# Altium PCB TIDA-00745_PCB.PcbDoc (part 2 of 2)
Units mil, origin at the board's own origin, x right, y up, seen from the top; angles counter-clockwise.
Board outline 7745 x 3490 mil, 4 copper layers (Top Layer, Signal Layer 1, Signal Layer 2, Bottom Layer), stack 61.2 mil thick; 181 components, 60 nets, 404 pads, 89 vias.
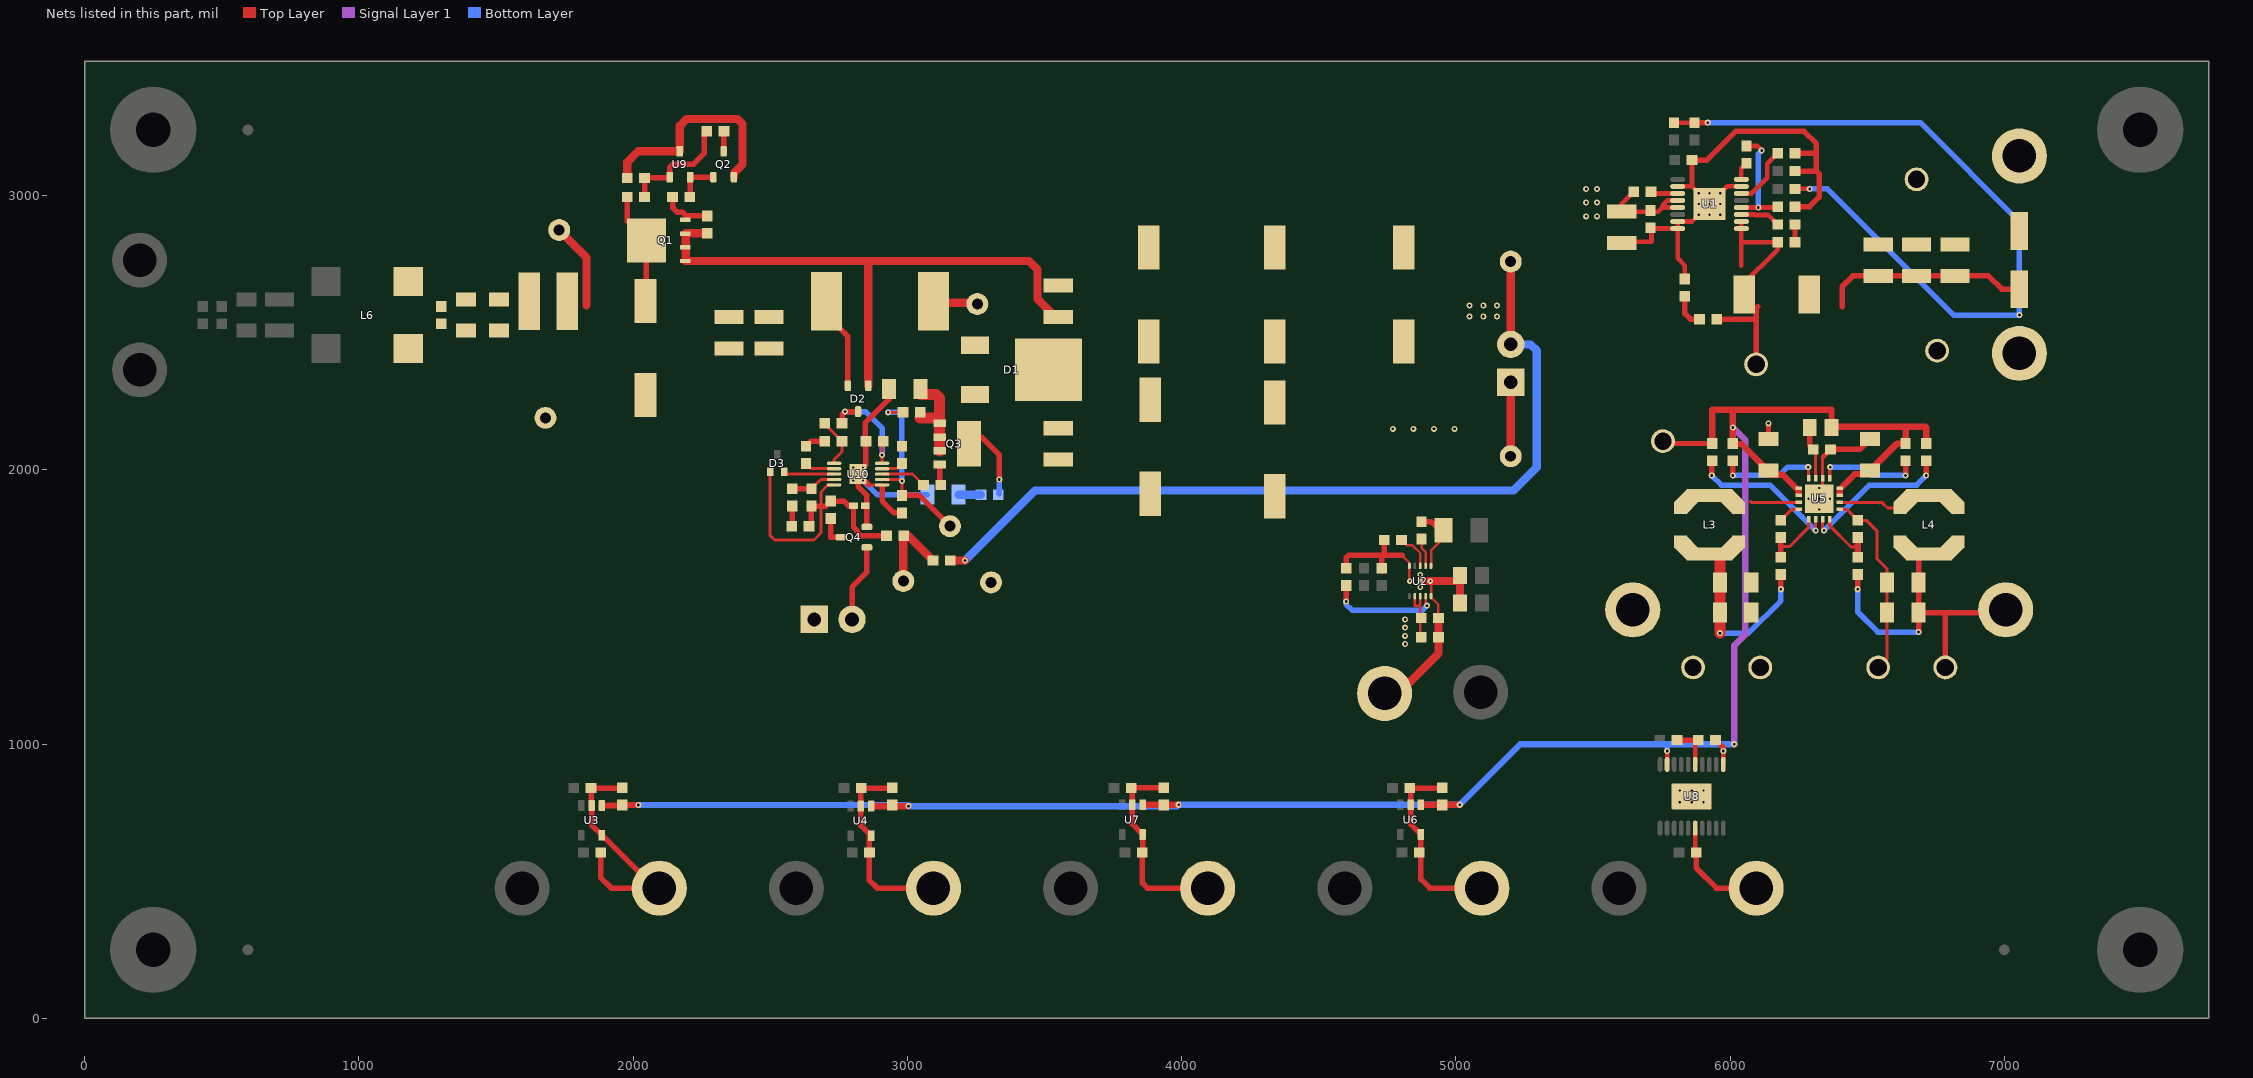
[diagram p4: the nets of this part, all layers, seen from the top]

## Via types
v1: diameter 22, hole 10, Top Layer to Bottom Layer, 60 vias
v2: diameter 20, hole 8, Top Layer to Bottom Layer, 29 vias

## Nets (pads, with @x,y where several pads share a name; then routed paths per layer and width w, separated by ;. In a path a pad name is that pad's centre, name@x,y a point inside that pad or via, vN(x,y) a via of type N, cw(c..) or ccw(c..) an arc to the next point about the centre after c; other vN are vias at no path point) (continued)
GND: C1.2 C2.2 C3.2 C5.2 C6.2 C7.2 C8.2 C9.2 C10.2 C12.2 C13.2 C14.1 C15.1 C16.2 C17.2 C18.2 C19.2 C20.2 C21.2 C22.2 C23.2 C24.2 C25.2 C26.2 C27.2 C28.2 C29.2 C30.2 C31.2 C32.2 C33.2 C34.2 C35.2 C36.2 C37.2 C41.2 C43.2 C44.2 C45.2 C46.2 C47.2 C48.2 C49.2 C50.2 C51.2 C52.2 C53.2 C54.2 C55.1 C56.2 C57.2 C58.2 C61.2 CVCC1.1 D4.2 J1.1 J2.1 L6.3 Q2.2 Q4.2 R6.1 R8.1 R10.1 R11.1 R19.1 R20.1 R25.1 R29.1 R30.1 TP4.1 TP5.1 TP7.1 TP10.1 TP11.1 TP17.1 TP18.1 TP20.1 TP21.1 TP22.1 TP26.1 TP28.1 TP32.1 U1.7 U1.10 U1.15 U1.16 U1.17 U2.5 U2.10 U2.11 U3.2 U3.5 U4.2 U4.5 U5.4 U5.9 U5.14 U5.17 U6.2 U6.5 U7.2 U7.5 U8.6 U8.15 U8.21 U9.3 U10.6 U10.11 | length 10121.7
  Top Layer w9: 4803.66,1688.5 4830.63,1661.53 U2.5@4830.63,1650.12 4830.63,1605.63 ; 4909.37,1584.37 U2.10@4909.37,1539.88 4910,1539.25 4910,1535 4936.5,1508.5 C14.1@4936.5,1460
  Top Layer w11: 2859.37,1945.63 U10.6@2907.6,1945.63 ; R19.1@6185,1816.5 6225.12,1856.61 U5.4@6250.2,1856.61 ; U5.17@6337.8,1907.8 U5.14@6337.8,1969.8 6337.8,2046.3 ; U5.9@6399.8,1856.61 6424.88,1856.61 R20.1@6465,1816.5 6496.5,1816.5 6536.3,1776.7 6536.3,1675.28 6572.91,1638.66 C33.2@6572.91,1590 C34.2@6572.91,1480 6572.91,1312.91 TP21.1@6540,1280
  Top Layer w15: 6337.8,2046.3 C24.2@6366.5,2075
  Top Layer w17: C1.2@5605,2827.91 5609.02,2831.93 5713.07,2831.93 5713.07,2880.43 U1.16@5808.86,2880.43 ; U1.10@5808.86,3033.98 5861.02,3033.98 v2(5925,2970) ; C9.2@5835,2696.5 5835,2745.5 5808.86,2771.64 U1.16@5808.86,2880.43 ; R8.1@5861.02,3129.53 R8.1@5861.5,3130 ; U8.6@5872.8,693.86 5872.8,608.7 C36.2@5876.5,605 ; U8.15@5872.8,926.14 C37.2@5872.8,1015 ; U1.7@6041.14,3033.98 5988.98,3033.98 v2(5925,2970) ; U1.16@5808.86,2880.43 U1.15@5808.86,2906.02 5861.02,2906.02 v2(5885.63,2930.63) v2(5925,2970)
  Top Layer w20: C17.2@1881.5,605 1881.5,513.5 1920,475 TP10.1@2078.86,475 ; C20.2@1960,841.5 1958.5,840 C16.2@1846.5,840 1846.5,778.23 U3.2@1848.45,776.28 1849.53,775.2 1849.53,704.33 U3.5@1885.85,668.01 TP10.1@2078.86,475 ; TP10.1@2095,475 TP10.1@2078.86,475 ; C58.2@2630,2086.5 2648.5,2105 C55.1@2698.5,2105 ; v2(2837.72,2008.62) 2848.5,2019.41 C56.2@2848.5,2105 2846,2107.5 2846,2171 2932.91,2257.91 R29.1@2932.91,2275 ; Q4.2@2852.24,1792.4 2852.24,1907.65 2820,1939.9 v2(2820,1985) 2859.37,1945.63 ; U10.6@2907.6,1941.54 2907.6,1887.4 2951.5,1843.5 C61.2@2980,1843.5 ; C21.2@2943.5,840 C18.2@2831.5,840 2830,838.5 U4.2@2830,774.13 2830,703.27 2861.5,671.77 C19.2@2861.5,605 2861.5,503.5 2890,475 TP11.1@3095,475 ; C27.2@3816.5,840 3820,836.5 U7.2@3820,779.13 3820,708.27 U7.5@3857.4,670.87 3857.4,605.91 C28.2@3856.5,605 3856.5,493.5 3875,475 TP18.1@4095,475 ; C27.2@3817.99,841.5 C30.2@3935,841.5 ; R10.1@4600,1641.5 4600,1680 4608.5,1688.5 4740,1688.5 ; R11.1@4730,1631.5 R11.1@4730,1641.5 4730,1683.5 ; CVCC1.1@4738.5,1745 4738.5,1690 4740,1688.5 ; 4803.66,1688.5 4740,1688.5 ; C25.2@4831.5,840 C29.2@4948.5,840 ; C25.2@4835,836.5 U6.2@4835,779.13 4835,708.27 U6.5@4872.4,670.87 4872.4,507.6 4905,475 TP17.1@5095,475 ; C35.2@5806.5,1015 C37.2@5883.5,1015 ; 5861.02,3033.98 R8.1@5861.02,3129.53 ; R8.1@5861.5,3130 5915,3130 6020,3235 6270,3235 6315,3190 6315,3090 ; C36.2@5876.5,605 5876.5,548.5 5950,475 TP22.1@6095,475 ; C22.2@6140,2112.09 v1(6140,2170) ; C10.2@6236.5,2960 6290,2960 6325,2995 6325,3080 6315,3090 ; C3.2@6236.5,3090 6315,3090 ; R6.1@6236.5,3155 6315,3155 ; v2(6325,1895) U5.17@6337.8,1907.8 ; C24.2@6366.5,2075 6472.91,2075 C23.2@6510,2112.09
  Top Layer w30: R25.1@1978.5,3065 1978.5,3123.5 2017.24,3162.24 U9.3@2170,3162.24 2170,3255 2195,3280 2380,3280 2398.9,3261.1 2398.9,3114.03 2367.4,3082.54 Q2.2@2367.4,3067.76 ; TP7.1@4740,1185 4790,1185 4936.5,1331.5 C15.1@4936.5,1390 C14.1@4936.5,1460 ; 4890,1595 v2(4907.4,1595) C13.2@5010,1595 ; C12.2@5015,1515 C13.2@5015,1615 ; TP28.1@5200,2050 J1.1@5200,2320
  Bottom Layer w20: v2(2837.72,1961.38) 2889.09,1910 R30.1@3072.91,1910
  other v2: 5816.69,788.35 5860,788.35 5903.31,788.35 5816.69,831.65 5860,831.65 5903.31,831.65 4870,1572.36 4832.6,1595 4870,1617.64 6325,1855.63 6285.63,1895 6364.37,1895 6325,1934.37 2802.28,1961.38 2802.28,2008.62 5925,2930.63 5964.37,2930.63 5885.63,2970 5964.37,2970 5885.63,3009.37 5925,3009.37 5964.37,3009.37
Net1_1: 1.1 C31.1 C32.1 L3.1 R16.2 TP12.1 | length 662.4
  Top Layer w20: v1(6185,1565) R16.2@6185,1618.5
  Top Layer w40: v1(5962.91,1405) C31.1@5962.91,1590 5962.91,1679.61 L3.1@5978,1694.7
  Bottom Layer w20: v1(5962.91,1405) 6067,1405 6185,1523 v1(6185,1565)
Net2_1: 2.1 C33.1 C34.1 L4.2 R18.2 TP15.1 | length 1183.8
  Top Layer w20: v1(6465,1565) R18.2@6465,1618.5 ; L4.2@6680,1693.7 6687.09,1686.61 C34.1@6687.09,1480 ; v1(6687.09,1409) C34.1@6687.09,1480 ; 2.1@6785,1280 6785,1480 ; TP15.1@6995,1480 6785,1480 ; C34.1@6687.09,1480 6785,1480
  Bottom Layer w20: v1(6465,1565) 6465,1483 6539,1409 v1(6687.09,1409)
NetC4_1: C4.1 R4.1 | length 65
  Top Layer w17: R4.1@6236.5,2830 C4.1@6236.5,2895
NetC4_2: C4.2 U1.3 | length 159.4
  Top Layer w17: U1.3@6041.14,2931.61 6089.67,2931.61 6091.46,2929.83 6138.67,2929.83 C4.2@6173.5,2895 C4.2@6165.12,2886.61
NetC9_1: C9.1 R5.1 | length 125.3
  Top Layer w20: C9.1@5835,2633.5 5835,2570 5855,2550 R5.1@5888.5,2550
NetC24_1: C24.1 R13.1 U5.15 | length 194.4
  Top Layer w11: C24.1@6303.5,2075 6312.2,2066.3 U5.15@6312.2,1969.8
  Top Layer w20: R13.1@6290,2155 6290,2088.5 C24.1@6303.5,2075
NetC43_1: C43.1 C44.1 C45.1 L6.4 LF1.1
NetC55_2: C55.2 R26.1 U10.1 | length 183.8
  Top Layer w11: R26.1@2698.5,2170 2698.5,2167.99 C55.2@2761.5,2105 2761.5,2066.5 2732.4,2037.4 U10.1@2732.4,2024.37
NetC56_1: C56.1 D2.3 R26.2 U10.10 | length 435
  Top Layer w11: U10.10@2907.6,2024.37 v1(2907.6,2055) 2907.6,2101.1 C56.1@2911.5,2105
  Top Layer w20: R26.2@2761.5,2170 2761.5,2202.01 v1(2772.24,2212.76) D2.3@2820,2212.76
  Bottom Layer w20: v1(2772.24,2212.76) 2847.24,2212.76 2907.6,2152.4 v1(2907.6,2055)
NetC57_1: C57.1 U10.9 | length 80.2
  Top Layer w11: U10.9@2907.6,2004.69 2961.18,2004.69 C57.1@2980,2023.5
NetC58_1: C58.1 U10.2 | length 110.2
  Top Layer w11: C58.1@2630,2023.5 2648.82,2004.69 U10.2@2732.4,2004.69
NetC59_1: C59.1 D1.1 D1.3 L5.2 Q3.5 TP29.1 | length 395.6
  Top Layer w20: 3269.98,2119.99 3335,2054.97 v1(3335,1965)
  Top Layer w30: L5.2@3094.88,2615 3099.88,2610 TP29.1@3255,2610
  Bottom Layer w20: C59.1@3335,1913.5 v1(3335,1965)
NetC59_2: C59.2 R30.2 | length 81.4
  Bottom Layer w30: R30.2@3187.09,1910 C59.2@3268.5,1910
NetC60_1: C60.1 C62.2 U10.4 | length 166.4
  Top Layer w11: C62.2@2650,1931.5 2683.82,1965.31 U10.4@2732.4,1965.31
  Top Layer w20: C60.1@2580,1931.5 C62.2@2650,1931.5
NetC60_2: C60.2 R31.2 | length 74.1
  Top Layer w20: R31.2@2578.5,1795 2580,1796.5 C60.2@2580,1868.5
NetC61_1: C61.1 R28.1 TP30.1 U10.7 | length 699.7
  Top Layer w11: U10.7@2907.6,1965.31 2974.68,1965.31 v1(2980,1960) C61.1@2980,1906.5 ; v1@2935,2210 R28.1@2983.5,2210 R28.1@2988.5,2210
  Top Layer w20: C61.1@2980,1906.5 2980,1908.43 3041.57,1908.43 TP30.1@3155,1795
  Bottom Layer w20: v1(2930,2210) 2970,2210 2980,2200 v1(2980,1960)
NetC62_1: C62.1 D3.1 D4.1 R31.1 R32.1 R34.2 U10.5 | length 1089.4
  Top Layer w11: D3.1@2499.41,1993.5 2499.41,1760.59 2515,1745 2659.38,1745 2685,1770.62 2685,1868.5 2685,1920 2710.63,1945.63 U10.5@2732.4,1945.63
  Top Layer w20: R31.1@2650,1803.5 C62.1@2650,1868.5 2685,1868.5 2702.01,1868.5 R34.2@2720,1886.5 2768.5,1886.5 2785,1870 D4.1@2803.35,1870 2803.35,1791.65 2814.68,1780.31 2814.68,1776.65 2831.33,1760 R32.1@2923.5,1760
NetCBOOT1_1: CBOOT1.1 U2.2 | length 105.3
  Top Layer w9: CBOOT1.1@4875,1748.5 4875,1715.36 4889.69,1700.67 U2.2@4889.69,1650.12 U2.2@4890.56,1650.12
NetCBOOT1_2: CBOOT1.2 L2.1 U2.1 | length 233.1
  Top Layer w9: U2.1@4909.37,1650.12 4909.37,1706.26 4955.04,1751.93 L2.1@4955.04,1765
  Top Layer w20: CBOOT1.2@4875,1811.5 4908.54,1811.5 L2.1@4955.04,1765
NetCVCC1_2: CVCC1.2 U2.3 | length 135
  Top Layer w9: CVCC1.2@4801.5,1745 4821.29,1725.2 4841.29,1725.2 4870,1696.5 U2.3@4870,1650.12
NetD3_2: D3.2 U10.3 | length 185.3
  Top Layer w11: D3.2@2550.59,1993.5 2559.09,1985 U10.3@2732.4,1985
NetJ2_2: J2.2 Q4.1 | length 285.1
  Top Layer w20: J2.2@2798,1455 2798,1573 2852.24,1627.24 Q4.1@2852.24,1717.6
NetL3_2: L3.2 U5.3 | length 178
  Top Layer w11: 6073.67,1885.68 6077.15,1882.2 U5.3@6250.2,1882.2
NetL4_1: L4.1 U5.10 | length 227.5
  Top Layer w11: U5.10@6399.8,1882.2 6553.01,1882.2 6573.7,1861.52 L4.1@6618.7,1861.52
NetQ1_4: Q1.4 R21.1 R24.2 | length 177.4
  Top Layer w20: R24.2@2143.5,2995 2143.5,2956.5 2160,2940 2180,2940 2193.5,2926.5 R21.1@2270,2926.5
NetQ2_1: Q2.1 R24.1 U9.2 | length 157
  Top Layer w20: R24.1@2207.4,2995.91 U9.2@2207.4,3067.76 Q2.1@2292.6,3067.76
NetQ2_3: Q2.3 R22.1 | length 73.4
  Top Layer w20: Q2.3@2330,3162.24 2330,3233.5 R22.1@2331.5,3235
NetQ3_1: Q3.1 Q3.2 Q3.3 R28.2 R29.2 | length 319.4
  Top Layer w40: 3046.5,2190 3097.72,2190 ; R29.2@3047.09,2275 3105,2275 3117.72,2262.28 Q3.1@3117.72,2170 Q3.2@3117.72,2120 Q3.3@3117.72,2070
NetQ3_4: Q3.4 R27.2 | length 76.6
  Top Layer w20: Q3.4@3117.72,2020 3117.72,1948.78 R27.2@3121.5,1945
NetQ4_3: Q4.3 R34.1 | length 106.3
  Top Layer w20: R34.1@2720,1823.5 2720,1755 Q4.3@2757.76,1755
NetR2_1: R2.1 U1.11 | length 98.8
  Top Layer w17: R2.1@5711.5,3005 5714.88,3008.39 U1.11@5808.86,3008.39
NetR3_1: R3.1 U1.8 | length 66.7
  Top Layer w17: U1.8@6041.14,3059.57 6041.14,3099.65 R3.1@6060,3118.5
NetR10_2: R10.2 U2.9 | length 416.3
  Top Layer w9: U2.9@4889.69,1539.88 4889.69,1510.31 v1(4895,1505)
  Top Layer w20: v1(4600,1520) R10.2@4600,1578.5
  Bottom Layer w20: v1(4600,1520) 4600,1510 4621.46,1488.54 4878.54,1488.54 v1(4895,1505)
NetR12_1: R12.1 U5.16 | length 378.5
  Top Layer w11: U5.16@6286.61,1969.8 v1@6286.61,2008.39
  Top Layer w20: v1(6010,1980) R12.1@6010,2033.5
  Bottom Layer w20: v1@6011,1980 6180,1980 6210,2010 v1(6285,2010)
NetR14_1: R14.1 U5.13 | length 378.9
  Top Layer w11: U5.13@6363.39,1969.8 6363.39,2008.39 v1(6365,2010)
  Top Layer w20: v1(6640,1980) R14.1@6640,2030.57
  Bottom Layer w20: v1(6365,2010) 6488.01,2010 6518.01,1980 v1(6640,1980)
NetR15_2: R15.2 U5.6 | length 554.1
  Top Layer w11: v1(6312,1779) 6312,1819.99 U5.6@6312.2,1820.2
  Top Layer w20: v1(5933,1980) R15.2@5933,2030.57
  Bottom Layer w20: v1(5933,1980) 5968,1945 6146,1945 v1(6312,1779)
NetR16_1: R16.1 R19.2 U5.5 | length 231
  Top Layer w11: 6186,1721 6217,1721 6286.61,1790.61 U5.5@6286.61,1820.2
  Top Layer w20: R16.1@6185,1681.5 R19.2@6185,1753.5
NetR17_2: R17.2 U5.7 | length 552.7
  Top Layer w11: U5.7@6337.8,1820.2 6337.8,1783.2 v1(6342,1779)
  Top Layer w20: v1(6715,1980) R17.2@6715,2033.5
  Bottom Layer w20: v1(6342,1779) 6508,1945 6680,1945 v1(6715,1980)
NetR18_1: R18.1 R20.2 U5.8 | length 229.7
  Top Layer w11: U5.8@6363.39,1820.2 6363.39,1797.39 6363,1797 6441,1719 6465,1719
  Top Layer w23: R18.1@6465,1681.5 6465,1719 R20.2@6465,1753.5
NetR22_2: R22.2 R23.1 R25.2 U9.1 | length 429.7
  Top Layer w20: R23.1@2041.5,2995 R25.2@2041.5,3065 2129.84,3065 U9.1@2132.6,3067.76 2132.6,3102.6 2145,3115 2220,3115 2260,3155 2260,3226.5 R22.2@2268.5,3235
NetR27_1: R27.1 U10.8 | length 167.5
  Top Layer w11: U10.8@2907.6,1985 3018.5,1985 R27.1@3058.5,1945
NetR32_2: R32.2 R33.1 TP31.1 | length 309.9
  Top Layer w30: TP31.1@2985,1595 2985,1758.5 R32.2@2986.5,1760 3003.5,1760 R33.1@3093.5,1670
SW: L1.1 R4.2 R5.2 TP2.1 U1.1 U1.2 | length 852.5
  Top Layer w17: 6041.14,2744.64 U1.1@6041.14,2880.43 U1.2@6041.14,2906.02 ; L1.1@6045,2675 6173.5,2803.5 R4.2@6173.5,2830 6046.14,2830
  Top Layer w20: R5.2@5951.5,2550 6095,2550 ; TP2.1@6095,2385 6095,2550 ; 6100,2595 6095,2590 6095,2550
SYNC: R6.2 U1.6 | length 223.2
  Top Layer w17: U1.6@6041.14,3008.39 6078.21,3008.39 6135,3065.18 6135,3116.5 R6.2@6173.5,3155
VCC: C10.1 R3.2 U1.4 | length 407
  Top Layer w17: U1.4@6041.14,2957.2 v1(6102.8,2957.2) C10.1@6173.5,2957.2 ; R3.2@6060,3181.5 6098.5,3181.5 v1(6115,3165)
  Bottom Layer w20: v1(6102.8,2957.2) 6102.8,3152.8 v1(6115,3165)
VIN+: C41.1 C46.1 C47.1 D2.2 L5.1 LF1.2 Q1.5 R23.2 TP23.1 | length 1065
  Top Layer w20: R23.2@1978.5,2995 1978.5,2906.5 Q1.5@2047.99,2837 2047.99,2619.25 C41.1@2045,2616.26 ; L5.1@2705.12,2615 2705.12,2564.88 2782.6,2487.4 D2.2@2782.6,2307.24
  Top Layer w30: TP23.1@1730,2875 1830,2775 1830,2600
VOUT: C5.1 C6.1 C7.1 C8.1 C11.1 C20.1 C21.1 C22.1 C23.1 C29.1 C30.1 C37.1 L1.2 R1.2 R7.2 R12.2 R13.2 R14.2 R15.1 R17.1 TP1.1 TP3.1 TP16.1 U3.1 U4.1 U5.1 U5.2 U5.11 U5.12 U6.1 U7.1 U8.11 U8.19 | length 11584.7
  Top Layer w17: U8.19@5770.43,926.14 v1(5770.43,975) ; R7.2@5795,3266.5 C11.1@5870,3266.5 ; U8.11@5975.16,926.14 v1@5975.16,975 ; R1.2@6236.5,3025 v1(6290,3025)
  Top Layer w20: TP16.1@5755,2105 5763.5,2096.5 R15.1@5935,2096.5 ; C11.1@5870,3266.5 v1(5918.5,3266.5) ; C37.1@5946.5,1015 5975.08,986.42 v1(5975.08,975) ; 6408.11,2595 6408.11,2668.11 6447.91,2707.91 C6.1@6540,2707.91 C7.1@6680,2707.91 C8.1@6820,2707.91 6942.09,2707.91 6990.81,2659.19 C5.1@7054.51,2659.19
  Top Layer w23: U3.1@1885.85,776.28 C20.1@1957.78,776.28 ; C20.1@1960,778.5 v1(2018.5,778.5) ; U4.1@2867.4,774.13 v1(3004.13,774.13) ; U7.1@3857.4,779.13 v1(3989.13,779.13) ; U6.1@4872.4,779.13 v1(5014.13,779.13) ; R15.1@5935,2096.5 5935,2220 6010,2220 ; R12.2@6010,2091.5 R12.2@6010,2095 ; C22.1@6140,1982.91 6192.09,1982.91 6250.2,1924.8 6250.2,1915 ; C22.1@6140,1997.91 6137.09,1997.91 6040,2095 R12.2@6010,2095 ; 6399.8,1916 6399.8,1929.8 6455,1985 6497.09,1985 C23.1@6510,1997.91 6608.58,2096.5 R14.2@6640,2096.5 ; R14.2@6636.42,2087.91 6636.42,2099.45 6640,2103.03 6640,2157.05 ; R17.1@6715,2096.5 6715,2155 6712.95,2157.05 6640,2157.05 ; R12.2@6010,2095 R12.2@6010,2096.5 v1(6010,2155) 6010,2220 ; 6010,2220 6370,2220 R13.2@6370,2155 6372.05,2157.05 6640,2157.05
  Signal Layer 1 w23: v1(6010,2155) 6055,2110 6055,1400 6015,1360 v1(6015,1000)
  Bottom Layer w20: v1(5770.43,975) 5770.43,999.41 ; v1(5918.5,3266.5) 6693.5,3266.5 7055,2905 v1(7055,2565) 6815,2565 6355,3025 v1(6290,3025) ; v1(5975.08,975) 5975.08,999.41
  Bottom Layer w23: v1(2018.5,778.5) 2999.76,778.5 v1(3004.13,774.13) 3984.13,774.13 v1(3989.13,779.13) v1(5014.13,779.13) 5235,1000 v1(6015,1000)
VS: C1.1 C2.1 C14.2 C15.2 C48.1 C49.1 C50.1 C51.1 C52.1 C53.1 C54.1 D1.4 D2.1 J1.2 Q1.1 Q1.2 Q1.3 R2.2 R21.2 R33.2 TP24.1 U1.12 U1.13 U2.7 U2.8 | length 5830.4
  Top Layer w9: U2.7@4850.31,1539.88 4850.31,1505.31 4850.63,1505 4870,1505 ; U2.8@4870,1539.88 4870,1505 ; C15.2@4873.5,1390 4870,1393.5 4870,1505
  Top Layer w17: R2.2@5648.5,3015 5605,2971.5 C1.1@5605,2942.09 5737.09,2942.09 5757.44,2962.44 ; U1.13@5808.86,2957.2 5762.68,2957.2 5754.94,2964.94 5772.8,2982.8 U1.12@5808.86,2982.8
  Top Layer w30: R21.2@2270,2863.5 2191.62,2863.5 2191.62,2763.5 Q1.1@2190.12,2762 2855,2762 ; D2.1@2857.4,2307.24 2857.4,2759.6 2855,2762 ; R33.2@3156.5,1670 v1(3210,1670) ; C52.1@3550,2557.91 3539.69,2557.91 3473.98,2623.62 3473.98,2731.02 3443,2762 2855,2762 ; J1.2@5200,2458 TP24.1@5200,2760
  Bottom Layer w30: v1(3210,1670) 3465,1925 5210,1925 5295,2010 5295,2435 5272,2458 J1.2@5200,2458
  other v1: 4815,1365 4815,1395 4815,1425 4815,1455 4770,2150 4845,2150 4920,2150 4995,2150 5050,2560 5100,2560 5150,2560 5050,2600 5100,2600 5150,2600 5475,2925 5515,2925 5475,2975 5515,2975 5475,3025 5515,3025
pads on no net: D3.3 FID1.1 FID2.1 FID3.1 FID4.1 FID5.1 FID6.1 H1.1 H2.1 H3.1 H4.1 LBL1.0 U1.14 U2.6 U8.2 U8.3 U8.4 U8.5 U8.7 U8.8 U8.9 U8.12 U8.13 U8.14 U8.16 U8.17 U8.18

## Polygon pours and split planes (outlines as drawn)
VS on Top Layer "Top Layer-VS" (solid, remove dead copper, pour order 28): 4875,1600 4875,1538.54 4900,1538.54 4900,1405 4895,1400 4790,1400 4790,1540 4790,1555 4805,1555 4850,1555 4848.17,1557.46 4848.17,1605 4875,1605
GND on Top Layer "Top Layer-GND" (solid, remove dead copper, pour order 38): 6390,1860 6550,1860 6575,1835 6610,1800 6610,1650 6610,1215 6615,1210 6610,1215 6500,1215 6500,1778.54 6493.54,1785 6488.54,1790 6390,1790
Net2_1 on Top Layer "Top Layer-NET2_1" (solid, remove dead copper, pour order 26): 6579.33,1765 7115,1765 7115,1215 6634.45,1215 6634.45,1654.33 6579.33,1709.45 6585,1715.12 6585,1765
NetL4_1 on Top Layer "Top Layer-NETL4_1" (solid, remove dead copper, pour order 25): 6390,1870 6585,1870 6585,1820 6865.67,1820 6870.67,1815 6875,1819.33 6875,1950 6480,1950 6435,1905 6425,1895 6390,1895
GND on Top Layer "Top Layer-GND" (solid, remove dead copper, pour order 42): 0,3490 5350,3490 7745,3490 7745,0 0,0
NetC59_1 on Top Layer "Top Layer-NET C59_1" (solid, remove dead copper, pour order 30): 3035,2720 3295,2720 3295,2240 3320,2215 3365,2215 3365,1995 3180,1995 3170,2005 3170,2345 3130,2345 3035,2440
VS on Top Layer "Top Layer-BOOST_VOUT" (solid, remove dead copper, pour order 31): 3390,2510 3315,2510 3315,2655 3315,2740 2980,2740 2166.59,2740 2166.59,2875 3488.28,2875 3488.28,2640 3615,2640 3775,2640 3810,2640 5250,2640.01 5250,2615 5250,2400 5220,2370 5050,2370 5050,2075 5060,2065 5035,2090 3390,2090
NetQ3_1 on Top Layer "Top Layer-NETQ3_1" (solid, remove dead copper, pour order 29): 3020,2330.43 3139.57,2330.43 3140,2330 3139.83,2329.83 3139.83,2059.96 3140,2059.79 3140,2050 3020,2050
VOUT on Top Layer "Top Layer-VOUT" (solid, remove dead copper, pour order 33): 6205,2761.31 6205,2320 5963.54,2320 5963.54,2065 7185,2065 7185,2761.31
SW on Top Layer "Top Layer-SW" (solid, remove dead copper, pour order 34): 6015,2909.74 6015,2534.97 6024.97,2525 6195,2525 6195,2865 6135,2865 6089.98,2910.02
VS on Top Layer "Top Layer-VS" (solid, remove dead copper, pour order 32): 5839.02,2995 5675,2995 5675,3065 5450,3065 5450,2900 5728.54,2900 5773.54,2945 5785,2945 5839.02,2945
GND on Top Layer "Top Layer-GND" (solid, remove dead copper, pour order 39): 5865,2980 5865,2925 5780,2925 5765,2910 5740,2910 5675,2910 5660,2895 5645,2880 5530,2880 5530,2675 5870,2675 6000,2675 6000,2980
GND on Top Layer "Top Layer-GND" (solid, remove dead copper, pour order 40): 6350,2780 6350,3275 7200,3275 7200,2780
GND on Top Layer "Top Layer-GND" (solid, remove dead copper, pour order 41): 6050,1215 6050,1399 6050,1657 6078,1685 6078,1872 6262,1872 6268,1866 6267,1865 6267,1792 6170,1792 6167,1789 6163,1785 6163,1215
NetL3_2 on Top Layer "Top Layer-NETL3_2" (solid, remove dead copper, pour order 36): 6255.14,1898 6232,1898 6181,1949 6136,1949 5828,1949 5792,1949 5792,1822 6073,1822 6073,1863 6216,1863 6219,1866 6223,1870 6265,1870 6265,1898
Net1_1 on Top Layer "Top Layer-NET1_1" (solid, remove dead copper, pour order 35): 5535,1765 5535,1215 6025,1215 6025,1661 6071,1707 6071,1765
GND on Top Layer "Top Layer-GND" (solid, remove dead copper, pour order 37): 5060,1645 4907.4,1645 4905,1642.6 4905,1400 4865,1360 4760,1360 4615,1360 4615,1105 4955,1105 4955,1330 5060,1435
NetCBOOT1_2 on Top Layer "Top Layer-NET CBOOT1_2" (solid, remove dead copper, pour order 27): 4900,1690 4990,1690 4990,1885 4852.72,1885 4847.73,1889.98 4850,1887.72 4850,1835 4900,1835
GND on Bottom Layer "Bottom Layer-GND" (solid, remove dead copper, pour order 47): 0,3490 7745,3490 7745,0 0,0
VS on Signal Layer 1 "Signal Layer 1-VOUT_BOOST" (solid, remove dead copper, pour order 44): 5575,3050 5575,2525 5575,2400 5025,2400 5025,2850 5225,3050 5475,3050
VS on Signal Layer 1 "Signal Layer 1-VOUT_BOOST" (solid, remove dead copper, pour order 43): 5150,2200 5150,1335 4540,1335 4540,2200 4670,2200
GND on Signal Layer 1 "Signal Layer 1-GND" (solid, remove dead copper, pour order 45): 0,3500 7750,3500 7750,0 0,0
GND on Signal Layer 2 "Signal Layer 2-GND" (solid, remove dead copper, pour order 46): 0,3500 7750,3500 7750,0 0,0

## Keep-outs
Keep-Out Layer:
  the board outline again, w10
  text ".Layer_Name" at 577,-3393.49 h60

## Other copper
Top Layer:
  region net VS: 4850.31,1550 4850.31,1475 4870,1475 4870,1550
  rectangle net VIN+: 1890,2645 2125,2940
  rectangle net VIN+: 1725,2510 2765,2720
  rectangle net GND: 1110,2375 1557.64,2555
  rectangle net NetC43_1: 1110,2595 1670,2775
  rectangle net BAT-: 100,2235 940,2545
  rectangle net BAT+: 100,2595 934.5,2899.5
  rectangle net SW: 6015,2865 6070,2909.76
  rectangle net GND: 2868.45,1932.57 2941.3,1950.16
  rectangle net VS: 4745,1345 4895,1480
  rectangle net 6V: 5070,1220 5135,1825
  rectangle net NetCBOOT1_2: 4909.37,1690 4925.51,1713.07
  pour cut-out: 5770,3025 6115,3025 6140,3000 6140,2940 6138.67,2938.67 6138.67,2929.83 6324.83,2929.83 6340,2945 6340,3200 6280,3260 6265,3260 6255,3250 5954.98,3250 5869.98,3165 5770,3165
  pour cut-out: 0,2975 1550,2975 1550,2175 0,2175
  text ".Layer_Name" at 577,-3393.49 h60
Signal Layer 1:
  pour cut-out: 0,2975 1550,2975 1550,2175 0,2175
Signal Layer 2:
  pour cut-out: 0,2975 1550,2975 1550,2175 0,2175
Bottom Layer:
  pour cut-out: -5,2165 1545,2165 1545,2965 -5,2965
  text ".Layer_Name" at 577,-3393.49 h60

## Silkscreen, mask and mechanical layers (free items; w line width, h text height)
Top Overlay:
  text ".PRJ_Number" at 2910,3205 h60
  text ".PCB_Rev" at 3510,3205 h60
  text ".Layer_Name" at 577,-3393.49 h60
Bottom Overlay:
  text ".Layer_Name" at 577,-3393.49 h60
Top Paste:
  text ".Layer_Name" at 577,-3393.49 h60
Bottom Paste:
  text ".Layer_Name" at 577,-3393.49 h60
Top Solder:
  text ".Layer_Name" at 577,-3393.49 h60
  text ".Layer_Name" at 577,-3393.49 h60
Bottom Solder:
  text ".Layer_Name" at 577,-3393.49 h60
Drill Guide:
  text ".Layer_Name" at 577,-3393.49 h60
M1 Board Outline:
  the board outline again, w10
  text ".Layer_Name" at 577,-3393.49 h60
M2 Board Dimensions:
  rectangle: 0,-2810 125,-2685
  rectangle: 125,-2935 500,-2810
  lines w7: 0,-2810 1000,-2810 ; 125,-2935 125,-2685 ; 250,-2935 250,-2685 ; 500,-2935 500,-2685 ; 750,-2935 750,-2685 ; 0,-2935 1000,-2935 1000,-2685 0,-2685 0,-2935
  text ".Layer_Name" at 577,-3393.49 h60
M3 3D STEP Top:
  text ".Layer_Name" at 577,-3393.49 h60
M4 3D STEP Bottom:
  text ".Layer_Name" at 577,-3393.49 h60
M5 Assembly Top:
  lines w10: -292,-3465.17 6308,-3465.17 ; -292,-3261.83 6310,-3261.83 ; -292,-3058.5 -292,-3668.5 3713,-3668.5 6310,-3668.5 6310,-3058.5 -291.5,-3058.5 -291.5,-3668.5 1284,-3668.5 ; 2173,-3668.5 2173,-3058.5 ; 3440,-3261.83 3440,-3058.5 ; 4280,-3261.83 4280,-3058.5 ; 4902,-3675 4902,-3472.17
  text "COMPONENTS MARKED 'DNP' SHOULD NOT BE POPULATED." at 1153.5,-2853.5 h60
  text "ASSEMBLY VARIANT:" at 1153,-2969 h60
  text ".VariantName" at 2189,-2969 h60
  text "PCB VIEWED FROM TOP SIDE" at -228.5,-3190.67 h60
  text "BOARD #:" at 2248,-3190.67 h60
  text ".PRJ_Number" at 2793.5,-3190.67 h60
  text "REV:" at 3638,-3190.67 h60
  text ".PCB_Rev" at 3929.5,-3190.67 h60
  text "SVN REV:" at 4476,-3190.67 h60
  text ".VersionControl_RevNumber" at 4982,-3190.67 h60
  text "TID #:" at 2248,-3394 h60
  text ".TID" at 2793.5,-3394 h60
  text "PLOT NAME =" at -228.5,-3599.34 h60
  text ".plot_File_Name" at 577,-3599.34 h60
  text "GENERATED    :" at 2250,-3599.34 h60
  text ".Print_Date" at 3119.5,-3599.34 h60
  text ".Print_Time" at 3848.5,-3599.34 h60
  text "TEXAS INSTRUMENTS" at 5113,-3599.34 h60
M6 Assembly Bottom:
  lines w10: -292.5,-3262.33 6309.5,-3262.33 ; -290.5,-3465.67 6309.5,-3465.67 ; 1115.5,-3675.5 1115.5,-3472.67 ; 1737.5,-3262.33 1737.5,-3059 ; 2577.5,-3262.33 2577.5,-3059 ; 3844.5,-3669 3844.5,-3059 ; 4733.5,-3669 6309,-3669 6309,-3059 -292.5,-3059 -292.5,-3669 2304.5,-3669 6309.5,-3669 6309.5,-3059
  text "COMPONENTS MARKED 'DNP' SHOULD NOT BE POPULATED." at 6102,-2853 h60
  text ".VariantName" at 5058,-2969 h60
  text "ASSEMBLY VARIANT:" at 6097,-2969 h60
  text ".VersionControl_RevNumber" at 1035.5,-3191.17 h60
  text "SVN REV:" at 1541.5,-3191.17 h60
  text ".PCB_Rev" at 2088,-3191.17 h60
  text "REV:" at 2379.5,-3191.17 h60
  text ".PRJ_Number" at 3224,-3191.17 h60
  text "BOARD #:" at 3769.5,-3191.17 h60
  text "PCB VIEWED FROM BOTTOM SIDE" at 6246,-3191.17 h60
  text ".TID" at 3224,-3394.5 h60
  text "TID #:" at 3769.5,-3394.5 h60
  text "TEXAS INSTRUMENTS" at 904.5,-3599.84 h60
  text ".Print_Time" at 2169,-3599.84 h60
  text ".Print_Date" at 2898,-3599.84 h60
  text "GENERATED    :" at 3767.5,-3599.84 h60
  text ".plot_File_Name" at 5440.5,-3599.84 h60
  text "PLOT NAME =" at 6246,-3599.84 h60
M9 Title Sheet:
  drawing of 57 lines, arcs and shapes, not listed
  text "1" at 739.84,5501.5 h70
  text "2" at 3235.5,5501.5 h70
  text "3" at 5724.84,5501.5 h70
  text "4" at 8231.51,5501.5 h70
  text "5" at 10730.5,5501.5 h70
  text "6" at 13235.5,5501.5 h70
  text "A" at -416.5,4358.5 h70
  text "A" at 14383.5,4358.5 h70
  text "B" at -416.5,1978.5 h70
  text "B" at 14383.5,1978.5 h70
  text "C" at -416.5,-396.5 h70
  text "C" at 14383.5,-396.5 h70
  text "PROJECT TITLE:" at 11343.5,-2257.5 h45
  text ".PRJ_Title" at 11393.5,-2390.83 h70
  text "DESIGNED FOR:" at 11343.5,-2558.5 h45
  text ".PRJ_Customer" at 11393.5,-2698.5 h70
  text "D" at -416.5,-2766.5 h70
  text "D" at 14383.5,-2766.5 h70
  text "FILE NAME:" at 11343.5,-2858.5 h45
  text ".PCB_File_Name_No_Path" at 11393.5,-2978.5 h70
  text "Texas Instruments (TI) and/or its licensors do not warrant the accuracy or completeness of this specification" at 6374,-3140.34 h45
  text "ENGINEER:" at 11343.5,-3148.5 h45
  text "LAYOUT BY:" at 12848.5,-3148.5 h45
  text "or any information contained therein. TI and/or its licensors do not warrant that this design will meet" at 6329.01,-3253 h45
  text ".PRJ_Engineer" at 11393.5,-3303.49 h70
  text ".PCB_Layout" at 12899,-3303.49 h70
  text "the specifications, will be suitable for your application or fit for any particular purpose, or will operate in" at 6329.01,-3365.67 h45
  text ".Layer_Name" at 577,-3393.49 h60
  text "ALTIUM DESIGNER VERSION:" at 12848.5,-3458.5 h45
  text "an implementation. TI and/or its licensors do not warrant that the design is production worthy. You should" at 6329.01,-3478.33 h45
  text "completely validate and test your design implementation to confirm the system functionality for your application." at 6374,-3591 h45
  text ".print_Scale" at 11393.5,-3591.83 h70
  text ".Application_BuildNumber" at 12899,-3591.83 h70
  text "1" at 739.84,-3798.5 h70
  text "2" at 3235.5,-3798.5 h70
  text "3" at 5724.84,-3798.5 h70
  text "4" at 8231.51,-3798.5 h70
  text "5" at 10730.5,-3798.5 h70
  text "6" at 13235.5,-3798.5 h70
M10 Fab Notes:
  drawing of 189 lines, arcs and shapes, not listed
  text "DESIGN INFORMATION" at 12381.02,3493 h60
  text "MIN. TRACK WIDTH:" at 11736.46,3313 h60
  text "9" at 12832.7,3313 h60
  text "MIL" at 12987.46,3313 h60
  text "7.874" at 12680,3185 h60
  text "MIN. CLEARANCE:" at 11736.46,3181 h60
  text "MIL" at 12987.46,3181 h60
  text "MIN. VIA PAD SIZE:" at 11736.46,3049 h60
  text "22" at 12802.71,3049 h60
  text "MIL" at 12987.46,3049 h60
  text "0.152mm (6MIL)" at 12431.46,2907.29 h60
  text "MINIMUM ANNULAR RING" at 11407.23,2903 h60
  text "EXTERNAL" at 13139.46,2903 h60
  text "PER" at 11607.23,2785 h60
  text "IPC-D-275 CLASS 2 LEVEL C" at 11827.23,2785 h60
  text "MIL, HOLES" at 13315.46,2672.71 h60
  text "+/-" at 12923,2672 h60
  text "+/-" at 13777,2672 h60
  text "REGISTRATION TOLERANCES:" at 11407.23,2667 h60
  text "METAL" at 12607,2667 h60
  text "5" at 13183.2,2667 h60
  text "3" at 14016.2,2667 h60
  text "MIL" at 14132.46,2667 h60
  text "+/-" at 13777,2554 h60
  text "HOLE SIZE TOLERANCE (UNLESS OTHERWISE SPECIFIED):" at 11407.23,2549 h60
  text "3" at 14016.2,2549 h60
  text "MIL" at 14132.46,2549 h60
  text "MATERIAL:" at 11332.46,2339.54 h60
  text "FR4" at 13845,2200 h60
  text "FR-4 High Tg" at 12318.9,2199.21 h60
  text "X" at 13055,2195 h60
  text "FR-408" at 11753.46,2190.64 h60
  text "OTHER" at 13241.46,2190.64 h60
  text "62 MIL (1.6mm) +/-10%" at 12073.56,2027.92 h60
  text "THICKNESS:" at 11407.23,2023.64 h60
  text "X" at 11945.4,2023.64 h60
  text "OTHER" at 13358.46,2023.64 h60
  text "TOLERANCE:" at 11407.23,1865.64 h60
  text "X" at 12246.53,1865.64 h60
  text "ANSI IPC-6012 TYPE 3 CLASS 2" at 12433.48,1865.64 h60
  text "OTHER +/-" at 12433.46,1709.64 h60
  text "BOW & TWIST:" at 11407.23,1552.64 h60
  text "X" at 12246.53,1552.64 h60
  text "ANSI IPC-6012 TYPE 3 CLASS 2" at 12433.48,1552.64 h60
  text "OTHER +/-" at 12433.46,1394.13 h60
  text "DRILLING:" at 11332.46,1255.64 h60
  text "REFERENCE:" at 11407.23,1138.64 h60
  text "X" at 12055.46,1138.64 h60
  text "AS SHOWN" at 12242.46,1138.64 h60
  text "X" at 12956.46,1138.64 h60
  text "NC_DRILL FILES" at 13093.46,1138.64 h60
  text "PTH MIN COPPER THICKNESS:" at 11407.23,980.64 h60
  text "X" at 12757.46,980.64 h60
  text "1MIL" at 12894.46,980.64 h60
  text "OTHER" at 13391.46,980.64 h60
  text "BOARD FINISH:" at 11332.46,821.64 h60
  text "SILKSCREEN:" at 11487.68,703.64 h60
  text "X" at 12436.46,703.64 h60
  text "TOP" at 12562.46,703.64 h60
  text "X" at 12946.46,703.64 h60
  text "BOTTOM" at 13073.46,703.64 h60
  text "SILKSCREEN COLOR:" at 11487.68,536.64 h60
  text "X" at 12435.42,536.64 h60
  text "WHITE" at 12562.46,536.64 h60
  text "OTHER" at 13073.46,536.64 h60
  text "X" at 12566.42,377.44 h60
  text "GREEN" at 12693.46,377.44 h60
  text "OTHER" at 13311.46,377.44 h60
  text "SOLDER RESIST COLOR:" at 11487.68,366.64 h60
  text "X" at 12566.42,207.44 h60
  text "MATTE" at 12693.46,207.44 h60
  text "SEMI-GLOSS" at 13311,206.8 h60
  text "IMMERSION GOLD (ENIG)" at 12393.46,18.92 h60
  text "ENEPIG" at 13731,15.64 h60
  text "SURFACE FINISH:" at 11332.46,14.64 h60
  text "PBFREE HASL" at 13525,-130 h60
  text "X" at 12895,-140 h60
  text "IMM. TIN/SILVER OR EQUIV" at 11662,-142.36 h60
  text "OTHER" at 13093.46,-142.36 h60
  text "X" at 12205,-320 h60
  text "ARRAY/PANEL:" at 11332.46,-321.36 h60
  text "CUT AND TRIM PER M1 BOARD OUTLINE" at 12393.46,-325.65 h60
  text "N.C. ROUTE" at 12393.46,-477.36 h60
  text "V. SCORE" at 13259.46,-477.36 h60
  text "CERTIFICATION:" at 11332.46,-614.36 h60
  text "MATERIALS AND WORKMANSHIP FOR ALL PCBS" at 12057.46,-614.36 h60
  text "TO MEET OR EXCEED THE REQUIREMENTS OF:" at 12057.46,-712.36 h60
  text "X" at 11683.96,-848.87 h60
  text "ANSI IPC-A-600F CLASS ->" at 11822.96,-848.87 h60
  text "X" at 13462.02,-848.87 h60
  text "2" at 13580.96,-848.86 h60
  text "1" at 13265.96,-850.36 h60
  text "3" at 13934.96,-850.36 h60
  text "X" at 11686.02,-1008.36 h60
  text "UL 94V-0" at 11822.96,-1008.36 h60
  text "X" at 12498.02,-1008.36 h60
  text "RoHS" at 12634.96,-1008.36 h60
  text "OTHER" at 13279.36,-1008.36 h60
  text "PER ORDER" at 13676.42,-1008.36 h60
  text "ADDITIONAL REQUIREMENTS:" at 11332.46,-1149.36 h60
  text "MICROSECTION:" at 11407.23,-1264.36 h60
  text "YES" at 12312.96,-1264.36 h60
  text "REQUIRED" at 13174.46,-1420.51 h60
  text "BARE BOARD ELEC. TEST:" at 11407.23,-1423.36 h60
  text "NONE" at 12712.96,-1423.36 h60
  text "X" at 13047.46,-1423.36 h60
  text "PER ORDER" at 13766.46,-1423.36 h60
  text "MANUFACTURER'S UL:" at 11407.23,-1580.36 h60
  text "RAIL" at 12572.96,-1584.65 h60
  text "METAL" at 13064.77,-1584.65 h60
  text "X" at 13440,-1585 h60
  text "SILK" at 13576.46,-1584.65 h60
  text ".Layer_Name" at 577,-3393.49 h60
M11 Gerber Information:
  lines w10: -292,-3465.17 6308,-3465.17 ; -292,-3261.83 6310,-3261.83 ; -292,-3058.5 -292,-3668.5 3713,-3668.5 6310,-3668.5 6310,-3058.5 -291.5,-3058.5 -291.5,-3668.5 1284,-3668.5 ; 2173,-3668.5 2173,-3058.5 ; 3440,-3261.83 3440,-3058.5 ; 4280,-3261.83 4280,-3058.5 ; 4902,-3675 4902,-3472.17
  text "ALL ARTWORK VIEWED FROM TOP SIDE" at -228.5,-3190.67 h60
  text "BOARD #:" at 2248,-3190.67 h60
  text ".PRJ_Number" at 2793.5,-3190.67 h60
  text "REV:" at 3638,-3190.67 h60
  text ".PCB_Rev" at 3929.5,-3190.67 h60
  text "SVN REV:" at 4476,-3190.67 h60
  text ".VersionControl_RevNumber" at 4982,-3190.67 h60
  text "LAYER NAME =" at -228.5,-3393.49 h60
  text "TID #:" at 2248,-3394 h60
  text ".TID" at 2793.5,-3394 h60
  text "PLOT NAME =" at -228.5,-3599.34 h60
  text ".plot_File_Name" at 577,-3599.34 h60
  text "GENERATED    :" at 2250,-3599.34 h60
  text ".Print_Date" at 3119.5,-3599.34 h60
  text ".Print_Time" at 3848.5,-3599.34 h60
  text "TEXAS INSTRUMENTS" at 5113,-3599.34 h60
M12 Stackup:
  drawing of 408 lines, arcs and shapes, not listed
  text "Layer" at 7860,5164.75 h60
  text "Name" at 8269.91,5164.75 h60
  text "Material" at 9209.65,5164.75 h60
  text "Thickness" at 10069.42,5164.75 h60
  text "Constant" at 10719.26,5164.75 h60
  text "Board Layer Stack" at 11289.12,5164.75 h60
  text "1" at 7860,5044.75 h60
  text "Top Overlay" at 8269.91,5044.75 h60
  text "2" at 7860,4924.75 h60
  text "Top Solder" at 8269.91,4924.75 h60
  text "Solder Resist" at 9209.65,4924.75 h60
  text "0.40mil" at 10069.42,4924.75 h60
  text "3.5" at 10719.26,4924.75 h60
  text "3" at 7860,4804.75 h60
  text "Top Layer" at 8269.91,4804.75 h60
  text "Copper" at 9209.65,4804.75 h60
  text "1.40mil" at 10069.42,4804.75 h60
  text "4" at 7860,4684.75 h60
  text "Dielectric1" at 8269.91,4684.75 h60
  text "FR-4" at 9209.65,4684.75 h60
  text "26.00mil" at 10069.42,4684.75 h60
  text "4.2" at 10719.26,4684.75 h60
  text "5" at 7860,4564.75 h60
  text "Signal Layer 1" at 8269.91,4564.75 h60
  text "Copper" at 9209.65,4564.75 h60
  text "0.70mil" at 10069.42,4564.75 h60
  text "6" at 7860,4444.75 h60
  text "Dielectric 3" at 8269.91,4444.75 h60
  text "5.00mil" at 10069.42,4444.75 h60
  text "4.2" at 10719.26,4444.75 h60
  text "7" at 7860,4324.75 h60
  text "Signal Layer 2" at 8269.91,4324.75 h60
  text "Copper" at 9209.65,4324.75 h60
  text "0.70mil" at 10069.42,4324.75 h60
  text "8" at 7860,4204.75 h60
  text "Dielectric 2" at 8269.91,4204.75 h60
  text "26.00mil" at 10069.42,4204.75 h60
  text "4.2" at 10719.26,4204.75 h60
  text "9" at 7860,4084.75 h60
  text "Bottom Layer" at 8269.91,4084.75 h60
  text "Copper" at 9209.65,4084.75 h60
  text "1.40mil" at 10069.42,4084.75 h60
  text "10" at 7860,3964.75 h60
  text "Bottom Solder" at 8269.91,3964.75 h60
  text "Solder Resist" at 9209.65,3964.75 h60
  text "0.40mil" at 10069.42,3964.75 h60
  text "3.5" at 10719.26,3964.75 h60
  text "11" at 7860,3844.75 h60
  text "Bottom Overlay" at 8269.91,3844.75 h60
  text ".Layer_Name" at 577,-3393.49 h60
M13 Component Bodies Top:
  text ".Layer_Name" at 577,-3393.49 h60
M14 Component Bodies Bottom:
  text ".Layer_Name" at 577,-3393.49 h60
M15 Courtyards Top:
  text ".Layer_Name" at 577,-3393.49 h60
M16 Courtyards Bottom:
  text ".Layer_Name" at 577,-3393.49 h60
Drill Drawing:
  circle w1: c9072.72,-1612.6 r24.89
  lines w1: 9047.83,-2234.76 9047.83,-2184.99 9097.6,-2184.99 9097.6,-2234.76 9047.83,-2234.76 ; 9047.83,-2073 9060.27,-2060.56 9047.83,-2048.11 9060.27,-2048.11 9072.72,-2035.67 9085.16,-2048.11 9097.6,-2048.11 9085.16,-2060.56 9097.6,-2073 9085.16,-2073 9072.72,-2085.44 9060.27,-2073 9047.83,-2073 ; 9047.83,-1923.68 9047.83,-1898.79 9060.27,-1898.79 9060.27,-1886.35 9085.16,-1886.35 9085.16,-1898.79 9097.6,-1898.79 9097.6,-1923.68 9085.16,-1923.68 9085.16,-1936.12 9060.27,-1936.12 9060.27,-1923.68 9047.83,-1923.68 ; 9047.83,-1786.8 9060.27,-1761.92 9047.83,-1737.03 9072.72,-1749.47 9097.6,-1737.03 9085.16,-1761.92 9097.6,-1786.8 9072.72,-1774.36 9047.83,-1786.8 ; 9047.83,-1488.16 9047.83,-1438.39 9097.6,-1438.39 9097.6,-1488.16 9047.83,-1488.16 ; 9047.83,-1313.96 9072.72,-1289.07 9097.6,-1313.96 9072.72,-1338.84 9047.83,-1313.96 ; 9057.78,-1478.21 9057.78,-1448.35 9087.65,-1448.35 9087.65,-1478.21 9057.78,-1478.21
  lines w12: 8980,-2279.56 11098.02,-2279.56 ; 8980,-1234.32 11098.02,-1234.32 ; 9350.36,-2428.88 9350.36,-1085 ; 9707.36,-2428.88 9707.36,-1085 ; 10368.93,-2428.88 10368.93,-1085 ; 10653.07,-2428.88 10653.07,-1085 ; 8980,-2428.88 8980,-1085 11098.02,-1085 11098.02,-2428.88 8980,-2428.88
  text "Symbol" at 9069.59,-1189.52 h72
  text "Quantity" at 9395.16,-1189.52 h72
  text "Finished Hole Size" at 9752.16,-1189.52 h72
  text "Plated" at 10413.72,-1189.52 h72
  text "Hole Type" at 10697.86,-1189.52 h72
  text "29" at 9395.16,-1338.84 h60
  text "8.00mil (0.203mm)" at 9752.16,-1338.84 h60
  text "PTH" at 10413.72,-1338.84 h60
  text "Round" at 10697.86,-1338.84 h60
  text "60" at 9395.16,-1488.16 h60
  text "10.00mil (0.254mm)" at 9752.16,-1488.16 h60
  text "PTH" at 10413.72,-1488.16 h60
  text "Round" at 10697.86,-1488.16 h60
  text "8" at 9395.16,-1637.48 h60
  text "40.00mil (1.016mm)" at 9752.16,-1637.48 h60
  text "PTH" at 10413.72,-1637.48 h60
  text "Round" at 10697.86,-1637.48 h60
  text "4" at 9395.16,-1786.8 h60
  text "50.00mil (1.270mm)" at 9752.16,-1786.8 h60
  text "PTH" at 10413.72,-1786.8 h60
  text "Round" at 10697.86,-1786.8 h60
  text "8" at 9395.16,-1936.12 h60
  text "63.00mil (1.600mm)" at 9752.16,-1936.12 h60
  text "PTH" at 10413.72,-1936.12 h60
  text "Round" at 10697.86,-1936.12 h60
  text "18" at 9395.16,-2085.44 h60
  text "122.05mil (3.100mm)" at 9752.16,-2085.44 h60
  text "PTH" at 10413.72,-2085.44 h60
  text "Round" at 10697.86,-2085.44 h60
  text "4" at 9395.16,-2234.76 h60
  text "125.98mil (3.200mm)" at 9752.16,-2234.76 h60
  text "PTH" at 10413.72,-2234.76 h60
  text "Round" at 10697.86,-2234.76 h60
  text "131 Total" at 9395.16,-2384.08 h60
  text ".Layer_Name" at 577,-3393.49 h60

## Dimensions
0,-2935 to 1000,-2935 on M2 Board Dimensions
0,0 to 0,3490 on M2 Board Dimensions
0,0 to 7745,0 on M2 Board Dimensions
